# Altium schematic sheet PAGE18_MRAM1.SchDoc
size 381 x 381 mm; SheetNumber: 19; SheetTotal: 28
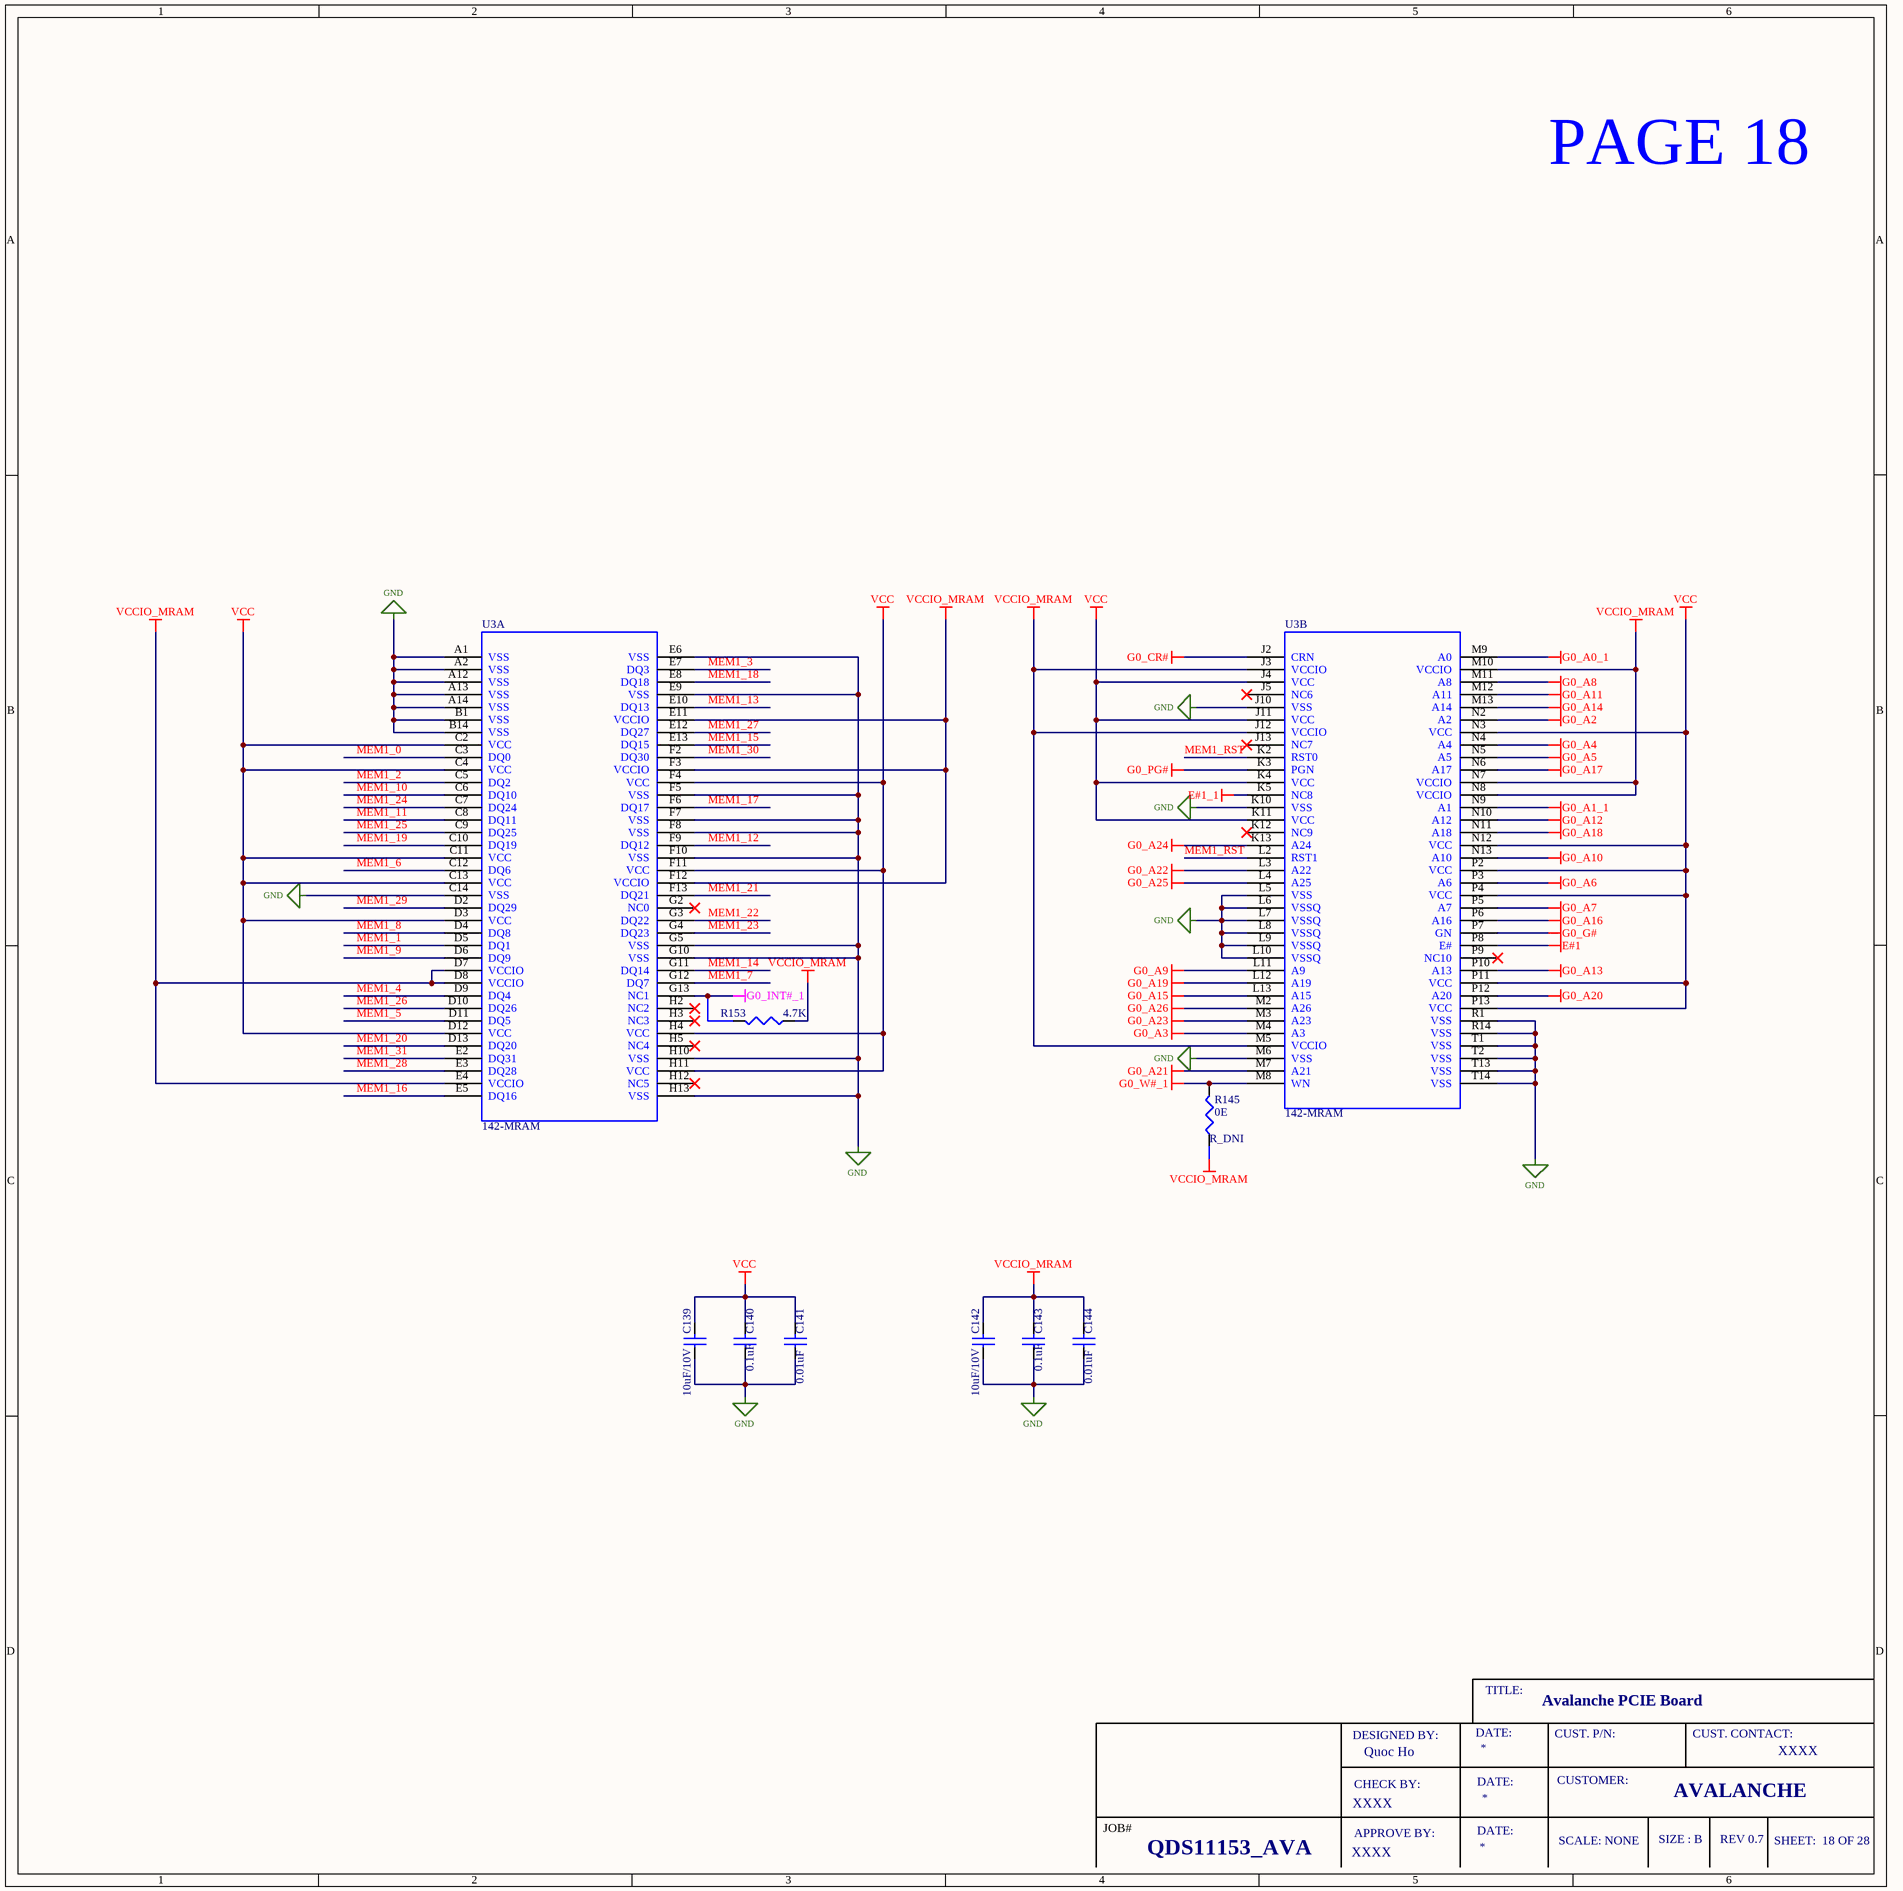
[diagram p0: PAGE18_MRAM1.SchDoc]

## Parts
C139  10uF/10V  [CN_0402]
C140  0.1uF  [CN_0402]
C141  0.01uF  [CN_0402]
C142  10uF/10V  [CN_0402]
C143  0.1uF  [CN_0402]
C144  0.01uF  [CN_0402]
R145  0E  [RN_0402]
R153  4.7K  [RN_0402]
U3  142-MRAM  [142-MRAM]  (parts A,B of 2)

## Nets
E#1: U3.P8(E#)
E#1_1: U3.K5(NC8)
G0_A0_1: U3.M9(A0)
G0_A1_1: U3.N9(A1)
G0_A2: U3.N2(A2)
G0_A3: U3.M4(A3)
G0_A4: U3.N4(A4)
G0_A5: U3.N5(A5)
G0_A6: U3.P3(A6)
G0_A7: U3.P5(A7)
G0_A8: U3.M11(A8)
G0_A9: U3.L11(A9)
G0_A10: U3.N13(A10)
G0_A11: U3.M12(A11)
G0_A12: U3.N10(A12)
G0_A13: U3.P10(A13)
G0_A14: U3.M13(A14)
G0_A15: U3.L13(A15)
G0_A16: U3.P6(A16)
G0_A17: U3.N6(A17)
G0_A18: U3.N11(A18)
G0_A19: U3.L12(A19)
G0_A20: U3.P12(A20)
G0_A21: U3.M7(A21)
G0_A22: U3.L3(A22)
G0_A23: U3.M3(A23)
G0_A24: U3.K13(A24)
G0_A25: U3.L4(A25)
G0_A26: U3.M2(A26)
G0_CR#: U3.J2(CRN)
G0_G#: U3.P7(GN)
G0_INT#_1: R153.2 U3.G13(NC1)
G0_PG#: U3.K3(PGN)
G0_W#_1: R145.2 U3.M8(WN)
GND: C139.1 C140.1 C141.1 C142.1 C143.1 C144.1 U3.A1(VSS) U3.A2(VSS) U3.A12(VSS) U3.A13(VSS) U3.A14(VSS) U3.B1(VSS) U3.B14(VSS) U3.C14(VSS) U3.E6(VSS) U3.E9(VSS) U3.F5(VSS) U3.F7(VSS) U3.F8(VSS) U3.F10(VSS) U3.G5(VSS) U3.G10(VSS) U3.H10(VSS) U3.H13(VSS) U3.J10(VSS) U3.K10(VSS) U3.L5(VSS) U3.L6(VSSQ) U3.L7(VSSQ) U3.L8(VSSQ) U3.L9(VSSQ) U3.L10(VSSQ) U3.M6(VSS) U3.R1(VSS) U3.R14(VSS) U3.T1(VSS) U3.T2(VSS) U3.T13(VSS) U3.T14(VSS)
VCC: C139.2 C140.2 C141.2 U3.C2(VCC) U3.C4(VCC) U3.C11(VCC) U3.C13(VCC) U3.D3(VCC) U3.D12(VCC) U3.F4(VCC) U3.F11(VCC) U3.H4(VCC) U3.H11(VCC) U3.J4(VCC) U3.J11(VCC) U3.K4(VCC) U3.K11(VCC) U3.N3(VCC) U3.N12(VCC) U3.P2(VCC) U3.P4(VCC) U3.P11(VCC) U3.P13(VCC)
VCCIO_MRAM: C142.2 C143.2 C144.2 R145.1 R153.1 U3.D7(VCCIO) U3.D8(VCCIO) U3.E4(VCCIO) U3.E11(VCCIO) U3.F3(VCCIO) U3.F12(VCCIO) U3.J3(VCCIO) U3.J12(VCCIO) U3.M5(VCCIO) U3.M10(VCCIO) U3.N7(VCCIO) U3.N8(VCCIO)
MEM1_0: U3.C3(DQ0)
MEM1_1: U3.D5(DQ1)
MEM1_2: U3.C5(DQ2)
MEM1_3: U3.E7(DQ3)
MEM1_4: U3.D9(DQ4)
MEM1_5: U3.D11(DQ5)
MEM1_6: U3.C12(DQ6)
MEM1_7: U3.G12(DQ7)
MEM1_8: U3.D4(DQ8)
MEM1_9: U3.D6(DQ9)
MEM1_10: U3.C6(DQ10)
MEM1_11: U3.C8(DQ11)
MEM1_12: U3.F9(DQ12)
MEM1_13: U3.E10(DQ13)
MEM1_14: U3.G11(DQ14)
MEM1_15: U3.E13(DQ15)
MEM1_16: U3.E5(DQ16)
MEM1_17: U3.F6(DQ17)
MEM1_18: U3.E8(DQ18)
MEM1_19: U3.C10(DQ19)
MEM1_20: U3.D13(DQ20)
MEM1_21: U3.F13(DQ21)
MEM1_22: U3.G3(DQ22)
MEM1_23: U3.G4(DQ23)
MEM1_24: U3.C7(DQ24)
MEM1_25: U3.C9(DQ25)
MEM1_26: U3.D10(DQ26)
MEM1_27: U3.E12(DQ27)
MEM1_28: U3.E3(DQ28)
MEM1_29: U3.D2(DQ29)
MEM1_30: U3.F2(DQ30)
MEM1_31: U3.E2(DQ31)
MEM1_RST: U3.K2(RST0) U3.L2(RST1)

Not connected (* = marked no-connect by the designer): U3 G2(NC0)* H2(NC2)* H3(NC3)* H5(NC4)* H12(NC5)* J5(NC6)* J13(NC7)* K12(NC9)* P9(NC10)*

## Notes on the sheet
- PAGE 18
- TITLE:
- Avalanche PCIE Board
- DESIGNED BY:
- CHECK BY:
- Quoc Ho
- DATE:
- CUST. P/N:
- CUSTOMER:
- CUST. CONTACT:
- XXXX
- JOB#
- APPROVE BY:
- SCALE: NONE
- SIZE : B
- AVALANCHE
- REV 0.7
- SHEET:  18 OF 28
- QDS11153_AVA

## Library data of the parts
C139 C142 = CAP: CAP CER 10UF 10V X5R 0402; Manufacturer: Murata Electronics; Manufacturer Part Number: GRM155R61A106ME11D
C140 C143 = CAP: CAP CER 0.1UF 50V X7R 0402; Manufacturer: Murata Electronics; Manufacturer Part Number: GCM155R71H104KE02J
C141 = CAP: 0.01 µF, 25 V, 0402 [1005 Metric], ± 10%, X7R; Manufacturer: YAGEO; Manufacturer Part Number: CC0402JRX7R8BB103
C144 = CAP: 0.01 µF, 25 V, 0402 [1005 Metric], ± 10%, X7R; Manufacturer Part Number: CC0402JRX7R8BB103; Manufacturer: YAGEO
R145 = RES: RES 0 OHM JUMPER 1/16W 0402; Manufacturer Part Number: RC0402FR-070RL; Manufacturer: YAGEO
R153 = RES: RES 4.7K OHM 1% 1/16W 0402; Manufacturer Part Number: RC0402FR-134K7L; Manufacturer: YAGEO
U3 = 142-MRAM: IC 142-MRAM MEMORY; Manufacturer: Avalanche Technology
